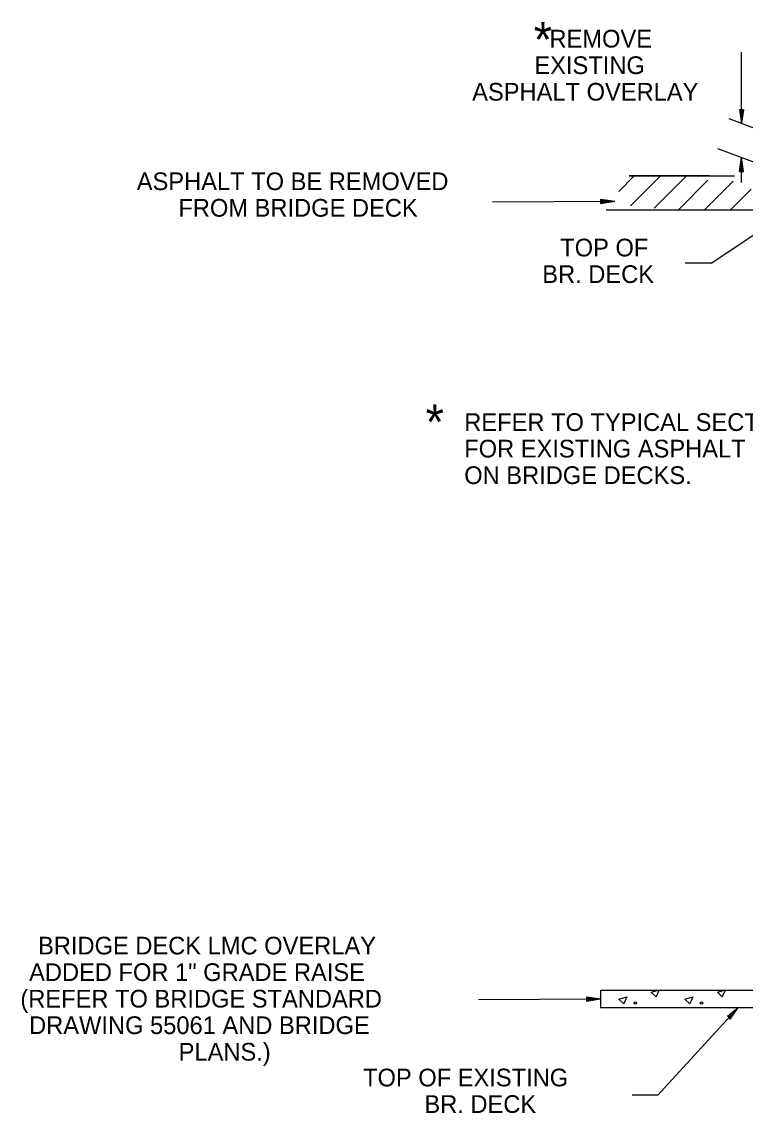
# Model space of a CAD drawing. Extents: x 1929624 to 1935547, y 596315 to 605721.
# Drawn here: x 1932986.9 to 1933232.2, y 602792.5 to 603162.6 of the extents above; entities that cross this region are included whole.
import ezdxf

# ---------------------------------------------------------------- set-up
doc = ezdxf.new("R2010")
doc.units = 0
doc.layers.add('Default', color=7, linetype='Continuous')
doc.layers.add('R_Border', color=7, linetype='Continuous')

msp = doc.modelspace()

# ---------------------------------------------------------------- linework, layer by layer
at = {"layer": 'Default'}
for p, q in [((1933230.93, 603128.29), (1933230.93, 603152.29)), ((1933230.26, 603132.74), (1933230.93, 603128.29)), ((1933230.26, 603132.74), (1933230.93, 603128.96)), ((1933231.59, 603132.74), (1933230.26, 603132.74)), ((1933230.49, 603132.74), (1933230.93, 603129.85)), ((1933230.49, 603132.74), (1933230.93, 603130.51)), ((1933230.71, 603132.74), (1933230.93, 603131.4)), ((1933230.71, 603132.74), (1933230.93, 603132.06)), ((1933231.59, 603132.74), (1933230.93, 603128.29)), ((1933231.14, 603132.74), (1933230.93, 603131.4)), ((1933231.38, 603132.74), (1933230.93, 603129.85)), ((1933231.38, 603132.74), (1933230.93, 603128.96)), ((1933231.14, 603132.74), (1933230.93, 603130.51)), ((1933230.93, 603132.74), (1933230.93, 603132.06)), ((1933278.31, 603110.36), (1933226.71, 603129.63)), ((1933278.31, 603098.82), (1933222.93, 603119.49)), ((1933230.26, 603111.83), (1933230.93, 603116.5)), ((1933230.26, 603111.83), (1933230.93, 603115.83)), ((1933230.49, 603111.83), (1933230.93, 603114.95)), ((1933230.49, 603111.83), (1933230.93, 603114.29)), ((1933231.59, 603111.83), (1933230.93, 603116.5)), ((1933230.93, 603108.06), (1933230.93, 603116.5)), ((1933231.38, 603111.83), (1933230.93, 603115.83)), ((1933231.38, 603111.83), (1933230.93, 603114.95)), ((1933231.14, 603111.83), (1933230.93, 603114.29)), ((1933230.26, 603111.83), (1933231.59, 603111.83)), ((1933230.71, 603111.83), (1933230.93, 603113.39)), ((1933230.71, 603111.83), (1933230.93, 603112.5)), ((1933231.14, 603111.83), (1933230.93, 603113.39)), ((1933230.93, 603111.83), (1933230.93, 603112.5)), ((1933189.29, 603105.07), (1933194.58, 603110.36)), ((1933192.86, 603110.36), (1933228.55, 603110.36)), ((1933193.25, 603100.19), (1933203.42, 603110.36)), ((1933201.27, 603099.37), (1933212.26, 603110.36)), ((1933209.55, 603098.82), (1933219.56, 603108.83)), ((1933218.39, 603098.82), (1933228.06, 603108.49)), ((1933227.23, 603098.82), (1933234.23, 603105.82)), ((1933146.49, 603101.55), (1933187.95, 603101.7)), ((1933183.24, 603100.98), (1933183.28, 603102.39)), ((1933183.24, 603102.09), (1933186.35, 603101.63)), ((1933183.24, 603100.98), (1933187.95, 603101.7)), ((1933183.28, 603102.39), (1933187.95, 603101.7)), ((1933183.29, 603101.29), (1933184.93, 603101.67)), ((1933183.29, 603101.29), (1933185.54, 603101.58)), ((1933183.34, 603101.59), (1933184.12, 603101.64)), ((1933183.34, 603101.59), (1933184.12, 603101.64)), ((1933183.38, 603101.9), (1933184.93, 603101.67)), ((1933183.38, 603101.9), (1933185.54, 603101.58)), ((1933183.41, 603102.21), (1933187.15, 603101.67)), ((1933183.42, 603101.11), (1933187.15, 603101.67)), ((1933183.42, 603101.11), (1933186.35, 603101.63)), ((1933185.06, 603098.82), (1933278.31, 603098.82)), ((1933220.64, 603080.71), (1933247.84, 603098.82)), ((1933220.64, 603080.71), (1933211.86, 603080.71)), ((1933141.72, 602831.05), (1933183.18, 602831.2)), ((1933178.46, 602830.48), (1933178.51, 602831.89)), ((1933178.46, 602830.48), (1933183.18, 602831.2)), ((1933178.47, 602831.59), (1933181.58, 602831.13)), ((1933178.51, 602831.89), (1933183.18, 602831.2)), ((1933178.52, 602830.79), (1933180.16, 602831.17)), ((1933178.52, 602830.79), (1933180.77, 602831.09)), ((1933178.56, 602831.1), (1933179.35, 602831.14)), ((1933178.56, 602831.1), (1933179.35, 602831.14)), ((1933178.61, 602831.4), (1933180.16, 602831.17)), ((1933178.61, 602831.4), (1933180.77, 602831.09)), ((1933178.64, 602831.72), (1933182.38, 602831.17)), ((1933178.64, 602830.62), (1933182.38, 602831.17)), ((1933178.64, 602830.62), (1933181.58, 602831.13)), ((1933183.18, 602828.32), (1933276.42, 602828.33)), ((1933202.59, 602798.52), (1933229.8, 602828.32)), ((1933226.14, 602825.36), (1933229.8, 602828.32)), ((1933226.33, 602825.12), (1933228.77, 602827.1)), ((1933226.35, 602825.33), (1933229.29, 602827.71)), ((1933226.56, 602825.09), (1933228.26, 602826.47)), ((1933226.56, 602825.09), (1933227.78, 602826.08)), ((1933226.95, 602824.61), (1933228.26, 602826.47)), ((1933226.95, 602824.61), (1933227.78, 602826.08)), ((1933227.14, 602824.37), (1933229.8, 602828.32)), ((1933227.16, 602824.59), (1933229.29, 602827.71)), ((1933227.16, 602824.59), (1933228.77, 602827.1)), ((1933227.14, 602824.37), (1933226.14, 602825.36)), ((1933226.76, 602824.86), (1933227.26, 602825.47)), ((1933226.76, 602824.86), (1933227.26, 602825.47)), ((1933202.59, 602798.52), (1933193.82, 602798.52))]:
    msp.add_line(p, q, dxfattribs=at)
msp.add_lwpolyline([(1933220.13, 603110.36), (1933192.86, 603110.36)], dxfattribs=at)
at = {"layer": 'R_Border'}
for p, q in [((1933262.56, 602834.1), (1933183.18, 602834.09)), ((1933183.18, 602834.09), (1933183.18, 602828.32)), ((1933200.29, 602833.54), (1933202.3, 602834.09)), ((1933201.95, 602831.9), (1933200.29, 602833.54)), ((1933202.93, 602834.09), (1933201.95, 602831.9)), ((1933222.75, 602833.54), (1933224.77, 602834.09)), ((1933224.41, 602831.9), (1933222.75, 602833.54)), ((1933225.38, 602834.09), (1933224.41, 602831.9)), ((1933189.32, 602831.16), (1933192.02, 602831.9)), ((1933190.98, 602829.52), (1933189.32, 602831.16)), ((1933192.02, 602831.9), (1933190.98, 602829.52)), ((1933211.77, 602831.16), (1933214.47, 602831.9)), ((1933213.43, 602829.52), (1933211.77, 602831.16)), ((1933214.47, 602831.9), (1933213.43, 602829.52))]:
    msp.add_line(p, q, dxfattribs=at)
msp.add_lwpolyline([(1933183.18, 602828.32), (1933276.42, 602828.33)], dxfattribs=at)
for centre in [(1933194.91, 602829.85), (1933194.91, 602829.85), (1933217.36, 602829.85), (1933217.36, 602829.85)]:
    msp.add_ellipse(centre, major_axis=(0, 0.411), ratio=0.9997, dxfattribs=at)

# ---------------------------------------------------------------- texts
at = {"layer": 'Default'}
for s, p in [(' REMOVE', (1933163.59, 603153.85)), ('EXISTING ', (1933160.71, 603144.85)), ('ASPHALT OVERLAY', (1933139.62, 603135.85)), ('ASPHALT TO BE REMOVED', (1933025.91, 603105.49)), (' FROM BRIDGE DECK', (1933037.79, 603096.49)), ('TOP OF ', (1933169.48, 603083.01)), ('BR. DECK', (1933163.38, 603074.01)), ('BRIDGE DECK LMC OVERLAY ', (1932992.44, 602846.29)), ('ADDED FOR 1" GRADE RAISE', (1932989.41, 602837.29)), ('(REFER TO BRIDGE STANDARD', (1932986.45, 602828.29)), ('DRAWING 55061 AND BRIDGE', (1932989.41, 602819.29)), (' PLANS.)', (1933037.88, 602810.29)), ('TOP OF EXISTING ', (1933102.63, 602801.55)), ('BR. DECK', (1933123.43, 602792.55))]:
    msp.add_text(s, height=6, rotation=360, dxfattribs=at).set_placement(p)
at = {"layer": 'R_Border'}
for s, height, p in [('*', 12, (1933160.48, 603150.56)), ('*', 12, (1933123.83, 603020.88)), ('REFER TO TYPICAL SECTIONS', 6, (1933136.93, 603023.82)), ('FOR EXISTING ASPHALT DEPTH ', 6, (1933136.93, 603014.82)), ('ON BRIDGE DECKS.', 6, (1933136.93, 603005.82))]:
    msp.add_text(s, height=height, rotation=360, dxfattribs=at).set_placement(p)

doc.saveas('drawing.dxf')
